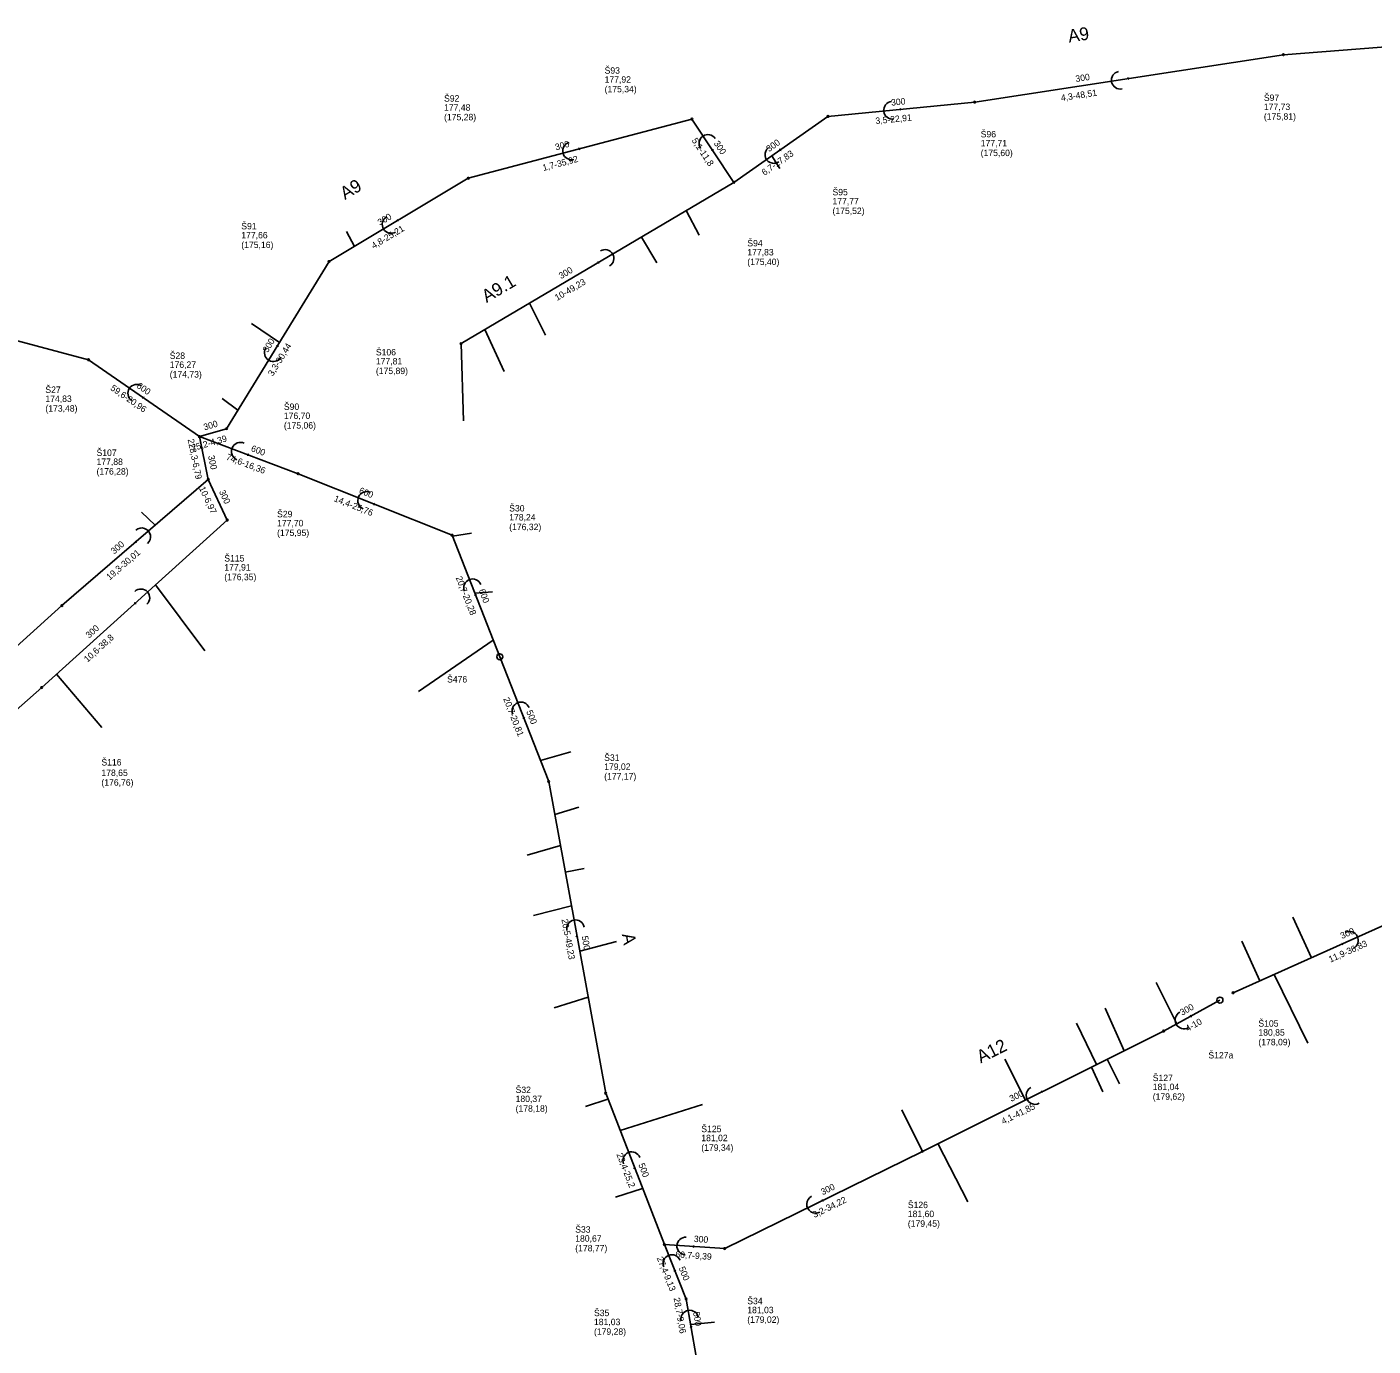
# Model space of a CAD drawing. Extents: x -548529 to -543591, y -1201432 to -1192608.
# Drawn here: x -546811.8 to -546602.8, y -1195130.1 to -1194925.2 of the extents above; entities that cross this region are included whole.
import ezdxf

# ---------------------------------------------------------------- set-up
doc = ezdxf.new("R2010")
doc.units = 0
for name, color, linetype in [('C3D_Bod-Značky', 7, 'Continuous'), ('C3D_Koridor', 7, 'Continuous'), ('C3D_Křižovatka', 7, 'Continuous'), ('C3D_Netisknutelná', 7, 'Continuous'), ('C3D_PP-zobrazeni v PR', 7, 'Continuous'), ('C3D_PR-Popisek', 7, 'Continuous'), ('C3D_SPR-Popisek', 7, 'Continuous'), ('C3D_Tlakove_potrubi_Popis', 7, 'Continuous'), ('C3D_ZPR-Formaty', 7, 'Continuous')]:
    doc.layers.add(name, color=color, linetype=linetype)

# ---------------------------------------------------------------- blocks, each defined once
blk = doc.blocks.new('100')
at = {"layer": 'Defpoints'}
blk.add_circle((0, 0), 0.127, dxfattribs=at)
blk = doc.blocks.new('101')
at = {"layer": 'Defpoints'}
blk.add_circle((0, 0), 0.463, dxfattribs=at)
blk = doc.blocks.new('91')
at = {"layer": 'Defpoints'}
blk.add_lwpolyline([(0.08, 0.14), (0.19, 0), (0.08, -0.14)], dxfattribs=at)
blk.add_arc((1.37, 0), 1.37, 270, 90, dxfattribs=at)
blk = doc.blocks.new('86')
at = {"layer": 'Defpoints'}
blk.add_lwpolyline([(0.08, 0.14), (0.19, 0), (0.08, -0.14)], dxfattribs=at)
blk.add_arc((1.37, 0), 1.37, 270, 90, dxfattribs=at)

msp = doc.modelspace()

# ---------------------------------------------------------------- linework, layer by layer
at = {"layer": 'C3D_Bod-Značky'}
for points in [[(-546569.03, -1194925.76), (-546616.67, -1194929.47)], [(-546616.67, -1194929.47), (-546664.62, -1194936.84)], [(-546664.62, -1194936.84), (-546687.417, -1194939.067)], [(-546708.549, -1194939.478), (-546743.272, -1194948.659)], [(-546702.016, -1194949.3), (-546708.549, -1194939.478)], [(-546687.417, -1194939.067), (-546702.016, -1194949.3)], [(-546743.272, -1194948.659), (-546764.903, -1194961.605)], [(-546744.402, -1194974.344), (-546702.016, -1194949.3)], [(-546764.903, -1194961.605), (-546780.799, -1194987.561)], [(-546802.25, -1194976.86), (-546840.07, -1194966.76)], [(-546785.018, -1194988.791), (-546802.25, -1194976.86)], [(-546780.799, -1194987.561), (-546785.018, -1194988.791)], [(-546783.658, -1194995.444), (-546785.018, -1194988.791)], [(-546769.704, -1194994.556), (-546785.018, -1194988.791)], [(-546806.389, -1195015.041), (-546783.658, -1194995.444)], [(-546780.716, -1195001.768), (-546783.658, -1194995.444)], [(-546745.786, -1195004.113), (-546769.704, -1194994.556)], [(-546809.519, -1195027.771), (-546780.716, -1195001.768)], [(-546738.383, -1195022.989), (-546745.786, -1195004.113)], [(-546843.032, -1195048.169), (-546806.389, -1195015.041)], [(-546730.785, -1195042.362), (-546738.383, -1195022.989)], [(-546846.428, -1195060.317), (-546809.519, -1195027.771)], [(-546721.933, -1195090.786), (-546730.785, -1195042.362)], [(-546624.49, -1195075.19), (-546590.87, -1195060.15)], [(-546626.536, -1195076.323), (-546635.297, -1195081.144)], [(-546635.297, -1195081.144), (-546672.747, -1195099.813)], [(-546712.823, -1195114.278), (-546721.933, -1195090.786)], [(-546672.747, -1195099.813), (-546703.452, -1195114.916)], [(-546703.452, -1195114.916), (-546712.823, -1195114.278)], [(-546709.433, -1195122.757), (-546712.823, -1195114.278)], [(-546707.859, -1195131.684), (-546709.433, -1195122.757)]]:
    msp.add_lwpolyline(points, dxfattribs=at)
at = {"layer": 'C3D_Koridor'}
for points in [[(-546696.143, -1194945.183), (-546694.865, -1194947.146)], [(-546709.426, -1194953.678), (-546707.408, -1194957.504)], [(-546760.958, -1194959.244), (-546762.19, -1194956.919)], [(-546716.39, -1194957.793), (-546713.995, -1194961.812)], [(-546733.783, -1194968.07), (-546731.27, -1194973.038)], [(-546772.597, -1194974.168), (-546776.951, -1194971.208)], [(-546740.712, -1194972.163), (-546737.689, -1194978.667)], [(-546744.402, -1194974.344), (-546743.999, -1194986.358)], [(-546779.046, -1194984.699), (-546781.5, -1194982.899)], [(-546791.877, -1195002.53), (-546793.999, -1195000.529)], [(-546745.721, -1195004.28), (-546742.788, -1195003.808)], [(-546791.842, -1195011.813), (-546784.198, -1195022.073)], [(-546742.261, -1195013.102), (-546739.522, -1195012.894)], [(-546739.387, -1195020.429), (-546751.015, -1195028.368)], [(-546807.233, -1195025.707), (-546800.207, -1195034.003)], [(-546732.07, -1195039.085), (-546727.356, -1195037.736)], [(-546729.851, -1195047.474), (-546726.086, -1195046.377)], [(-546728.966, -1195052.314), (-546734.109, -1195053.788)], [(-546728.207, -1195056.465), (-546725.26, -1195055.863)], [(-546727.25, -1195061.698), (-546733.169, -1195063.174)], [(-546612.322, -1195069.747), (-546615.228, -1195063.452)], [(-546620.318, -1195073.324), (-546623.13, -1195067.145)], [(-546725.966, -1195068.722), (-546720.244, -1195067.243)], [(-546618.1, -1195072.332), (-546612.91, -1195083.015)], [(-546633.221, -1195080.002), (-546636.447, -1195073.579)], [(-546724.661, -1195075.863), (-546729.917, -1195077.532)], [(-546641.392, -1195084.182), (-546644.35, -1195077.585)], [(-546645.705, -1195086.333), (-546648.802, -1195079.883)], [(-546656.758, -1195091.843), (-546659.942, -1195085.494)], [(-546644.059, -1195085.512), (-546642.138, -1195089.311)], [(-546646.484, -1195086.721), (-546644.697, -1195090.546)], [(-546721.58, -1195091.696), (-546725.054, -1195092.848)], [(-546719.682, -1195096.591), (-546706.895, -1195092.555)], [(-546672.747, -1195099.813), (-546675.928, -1195093.387)], [(-546670.326, -1195098.606), (-546665.677, -1195107.643)], [(-546716.2, -1195105.57), (-546720.426, -1195106.957)], [(-546708.732, -1195126.73), (-546705.026, -1195126.364)]]:
    msp.add_lwpolyline(points, dxfattribs=at)

# ---------------------------------------------------------------- block references
at = {"layer": 'C3D_PP-zobrazeni v PR'}
for name, p, xscale, yscale, rotation in [('100', (-546616.67, -1194929.47), 1.0098116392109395, 1.0098116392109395, -169.38969821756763), ('100', (-546664.62, -1194936.84), 1.0092050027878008, 1.0092050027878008, -168.88308178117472), ('100', (-546708.549, -1194939.478), 1.0296949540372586, 1.0296949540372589, 155.86620948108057), ('100', (-546687.417, -1194939.067), 1.0275072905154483, 1.027507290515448, -155.31089431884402), ('100', (-546743.272, -1194948.659), 1.0225848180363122, 1.0225848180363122, -154.18102564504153), ('100', (-546702.016, -1194949.3), 1.0073309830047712, 1.0073309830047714, 167.86109133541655), ('100', (-546764.903, -1194961.605), 0.999999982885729, 0.9999999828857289, -135), ('100', (-546744.402, -1194974.344), 1.0000000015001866, 1.0000000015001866, -149.00000017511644), ('100', (-546802.25, -1194976.86), 1.019856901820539, 1.0198569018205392, 153.606016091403), ('100', (-546780.799, -1194987.561), 1.000000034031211, 1.0000000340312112, -141.99999959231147), ('100', (-546785.018, -1194988.791), 0.9999999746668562, 0.999999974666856, 124.00000045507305), ('100', (-546783.658, -1194995.444), 0.999999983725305, 0.999999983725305, 109.00000122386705), ('100', (-546769.704, -1194994.556), 1.0275072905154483, 1.027507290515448, 155.31089431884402), ('100', (-546780.716, -1195001.768), 0.999999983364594, 0.9999999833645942, -101.0000002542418), ('100', (-546745.786, -1195004.113), 0.999999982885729, 0.9999999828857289, 135), ('100', (-546806.389, -1195015.041), 1.0000000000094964, 1.0000000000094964, -137.9999986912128), ('101', (-546738.383, -1195022.989), 1.0000000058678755, 1.0000000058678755, -68.00000099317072), ('100', (-546809.519, -1195027.771), 1.0000000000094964, 1.0000000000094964, -137.9999986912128), ('100', (-546730.785, -1195042.362), 0.9999999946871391, 0.9999999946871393, 106.00000024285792), ('100', (-546624.49, -1195075.19), 1.0169562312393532, 1.016956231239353, -153.02398354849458), ('101', (-546626.536, -1195076.323), 1.0037042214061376, 1.0037042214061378, 29.379208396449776), ('100', (-546635.297, -1195081.144), 1.0072562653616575, 1.0072562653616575, 28.76666512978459), ('100', (-546721.933, -1195090.786), 0.9999999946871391, 0.9999999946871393, 106.00000024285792), ('100', (-546672.747, -1195099.813), 1.0106518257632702, 1.0106518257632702, -151.83788426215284), ('100', (-546712.823, -1195114.278), 1.000000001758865, 1.000000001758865, 144.00000066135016), ('100', (-546703.452, -1195114.916), 1.0045862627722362, 1.0045862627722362, -166.82590928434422), ('100', (-546709.433, -1195122.757), 0.9999999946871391, 0.9999999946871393, 106.00000024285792)]:
    msp.add_blockref(name, p, dxfattribs=dict(at, xscale=xscale, yscale=yscale, rotation=rotation))
at = {"layer": 'C3D_SPR-Popisek'}
for name, p, xscale, yscale, rotation in [('91', (-546640.645, -1194933.155), 1.008377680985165, 1.0083776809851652, -168.37362119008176), ('91', (-546676.018, -1194937.954), 1.0011217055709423, 1.0011217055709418, -173.41739016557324), ('91', (-546705.282, -1194944.389), 0.9999999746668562, 0.999999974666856, 124.00000045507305), ('91', (-546725.91, -1194944.068), 0.999999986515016, 0.9999999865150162, -164.99999987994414), ('91', (-546694.716, -1194944.184), 1.000000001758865, 1.000000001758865, -144.00000066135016), ('91', (-546754.088, -1194955.132), 1.0000000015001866, 1.0000000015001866, -149.00000017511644), ('91', (-546723.209, -1194961.822), 1.0000000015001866, 1.0000000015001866, 30.99999982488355), ('91', (-546772.851, -1194974.583), 1.0000000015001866, 1.0000000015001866, -120.99999982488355), ('91', (-546793.634, -1194982.826), 0.9999999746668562, 0.999999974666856, 145.99999954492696), ('91', (-546777.361, -1194991.674), 1.0296949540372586, 1.0296949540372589, 155.86620948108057), ('91', (-546757.745, -1194999.334), 1.0275072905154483, 1.027507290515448, 155.31089431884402), ('91', (-546795.024, -1195005.242), 1.0000000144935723, 1.0000000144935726, 40.99999910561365), ('91', (-546742.085, -1195013.551), 1.0000000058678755, 1.0000000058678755, 111.99999900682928), ('86', (-546795.117, -1195014.77), 1.00000000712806, 1.00000000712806, 43.0000005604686), ('91', (-546734.584, -1195032.675), 1.0000000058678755, 1.0000000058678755, 111.99999900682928), ('91', (-546726.359, -1195066.574), 0.999999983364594, 0.9999999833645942, 101.0000002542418), ('91', (-546607.68, -1195067.67), 1.0169562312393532, 1.016956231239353, 26.97601645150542), ('91', (-546630.916, -1195078.734), 1.0037042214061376, 1.0037042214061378, -150.62079160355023), ('91', (-546654.022, -1195090.479), 1.0106518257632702, 1.0106518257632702, -151.83788426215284), ('91', (-546717.378, -1195102.532), 1.0000000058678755, 1.0000000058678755, 111.99999900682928), ('91', (-546688.1, -1195107.365), 1.0106518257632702, 1.0106518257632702, -151.83788426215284), ('91', (-546708.138, -1195114.597), 1.0002788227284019, 1.0002788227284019, 176.70930040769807), ('91', (-546711.128, -1195118.518), 1.0000000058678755, 1.0000000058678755, 111.99999900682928), ('91', (-546708.646, -1195127.22), 0.9999999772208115, 0.9999999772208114, 100.00000028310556)]:
    msp.add_blockref(name, p, dxfattribs=dict(at, xscale=xscale, yscale=yscale, rotation=rotation))

# ---------------------------------------------------------------- texts
at = {"layer": 'C3D_Křižovatka'}
for s, p in [('Š93', (-546722.099, -1194932.418)), ('Š92', (-546747.032, -1194936.759)), ('Š97', (-546619.71, -1194936.66)), ('Š96', (-546663.69, -1194942.32)), ('Š95', (-546686.707, -1194951.317)), ('Š91', (-546778.523, -1194956.605)), ('Š94', (-546699.936, -1194959.25)), ('Š106', (-546757.622, -1194976.184)), ('Š28', (-546789.638, -1194976.721)), ('Š27', (-546808.95, -1194982.01)), ('Š90', (-546771.909, -1194984.651)), ('Š107', (-546801.008, -1194991.794)), ('Š29', (-546772.964, -1195001.326)), ('Š30', (-546736.916, -1195000.423)), ('Š115', (-546781.166, -1195008.198)), ('Š476', (-546746.563, -1195026.989)), ('Š31', (-546722.165, -1195039.162)), ('Š116', (-546800.249, -1195039.881)), ('Š105', (-546620.56, -1195080.44)), ('Š127a', (-546628.326, -1195085.383)), ('Š127', (-546636.967, -1195088.904)), ('Š32', (-546735.923, -1195090.756)), ('Š125', (-546707.082, -1195096.836)), ('Š126', (-546675.007, -1195108.633)), ('Š33', (-546726.663, -1195112.448)), ('Š34', (-546699.943, -1195123.557)), ('Š35', (-546723.749, -1195125.414))]:
    msp.add_text(s, height=1, dxfattribs=at).set_placement(p)
at = {"layer": 'C3D_Netisknutelná'}
for s, rotation, p in [('A9', 8.74, (-546649.972, -1194927.592)), ('A9', 30.9, (-546762.424, -1194952.062)), ('A9.1', 30.58, (-546740.431, -1194968.049)), ('A', 280.36, (-546719.433, -1195066.109)), ('A12', 26.5, (-546663.684, -1195086.174))]:
    msp.add_text(s, height=2, rotation=rotation, dxfattribs=at).set_placement(p)
at = {"layer": 'C3D_PR-Popisek'}
for s, rotation, p in [('300', 8.74, (-546648.894, -1194933.718)), ('300', 5.58, (-546677.557, -1194937.398)), ('300', 14.81, (-546729.651, -1194944.337)), ('300', 303.63, (-546705.202, -1194943.237)), ('300', 35.03, (-546696.556, -1194944.616)), ('300', 30.9, (-546756.98, -1194956.045)), ('300', 30.58, (-546728.855, -1194964.348)), ('300', 58.52, (-546774.434, -1194975.822)), ('600', 325.3, (-546794.877, -1194981.118)), ('300', 16.25, (-546784.232, -1194987.833)), ('300', 281.55, (-546783.687, -1194991.804)), ('600', 339.37, (-546777.11, -1194991.016)), ('300', 294.95, (-546782.008, -1194997.34)), ('600', 338.22, (-546760.335, -1194997.548)), ('300', 40.77, (-546798.275, -1195007.117)), ('600', 291.41, (-546741.671, -1195012.681)), ('300', 42.08, (-546802.156, -1195020.178)), ('500', 291.41, (-546734.289, -1195031.502)), ('300', 24.1, (-546607.564, -1195066.85)), ('500', 280.36, (-546725.677, -1195066.422)), ('300', 28.82, (-546632.419, -1195078.761)), ('300', 26.5, (-546658.924, -1195092.139)), ('500', 291.2, (-546716.88, -1195101.873)), ('300', 26.19, (-546688.222, -1195106.643)), ('300', 356.11, (-546708.266, -1195113.886)), ('500', 291.79, (-546710.609, -1195117.935)), ('500', 280, (-546708.36, -1195124.821))]:
    msp.add_text(s, height=1, rotation=rotation, dxfattribs=at).set_placement(p)
at = {"layer": 'C3D_Tlakove_potrubi_Popis'}
for s, p in [('177,92 ', (-546722.099, -1194933.818)), ('(175,34)', (-546722.099, -1194935.318)), ('177,48 ', (-546747.032, -1194938.159)), ('177,73 ', (-546619.71, -1194938.06)), ('(175,28)', (-546747.032, -1194939.659)), ('(175,81)', (-546619.71, -1194939.56)), ('177,71 ', (-546663.69, -1194943.72)), ('(175,60)', (-546663.69, -1194945.22)), ('177,77 ', (-546686.707, -1194952.717)), ('(175,52)', (-546686.707, -1194954.217)), ('(175,16)', (-546778.523, -1194959.505)), ('177,66 ', (-546778.523, -1194958.005)), ('177,83 ', (-546699.936, -1194960.65)), ('(175,40)', (-546699.936, -1194962.15)), ('176,27 ', (-546789.638, -1194978.121)), ('177,81 ', (-546757.622, -1194977.584)), ('(174,73)', (-546789.638, -1194979.621)), ('(175,89)', (-546757.622, -1194979.084)), ('174,83 ', (-546808.95, -1194983.41)), ('(173,48)', (-546808.95, -1194984.91)), ('176,70 ', (-546771.909, -1194986.051)), ('(175,06)', (-546771.909, -1194987.551)), ('(176,28)', (-546801.008, -1194994.694)), ('177,88 ', (-546801.008, -1194993.194)), ('177,70 ', (-546772.964, -1195002.726)), ('(176,32)', (-546736.916, -1195003.323)), ('178,24 ', (-546736.916, -1195001.823)), ('(175,95)', (-546772.964, -1195004.226)), ('177,91 ', (-546781.166, -1195009.598)), ('(176,35)', (-546781.166, -1195011.098)), ('179,02 ', (-546722.165, -1195040.562)), ('(176,76)', (-546800.249, -1195043.011)), ('178,65 ', (-546800.249, -1195041.511)), ('(177,17)', (-546722.165, -1195042.062)), ('180,85 ', (-546620.56, -1195081.84)), ('(178,09)', (-546620.56, -1195083.34)), ('181,04 ', (-546636.967, -1195090.304)), ('180,37 ', (-546735.923, -1195092.156)), ('(179,62)', (-546636.967, -1195091.804)), ('(178,18)', (-546735.923, -1195093.656)), ('181,02 ', (-546707.082, -1195098.236)), ('(179,34)', (-546707.082, -1195099.736)), ('181,60 ', (-546675.007, -1195110.033)), ('(179,45)', (-546675.007, -1195111.533)), ('180,67 ', (-546726.663, -1195113.848)), ('(178,77)', (-546726.663, -1195115.348)), ('(179,02)', (-546699.943, -1195126.457)), ('181,03 ', (-546699.943, -1195124.957)), ('(179,28)', (-546723.749, -1195128.314)), ('181,03 ', (-546723.749, -1195126.814))]:
    msp.add_text(s, height=1, dxfattribs=at).set_placement(p)
at = {"layer": 'C3D_ZPR-Formaty'}
for s, rotation, p in [('4,3-48,51', 8.74, (-546651.157, -1194936.691)), ('3,5-22,91', 5.58, (-546679.988, -1194940.254)), ('5,1-11,8', 303.63, (-546708.614, -1194942.809)), ('1,7-35,92', 14.81, (-546731.594, -1194947.54)), ('6,7-17,83', 35.03, (-546697.274, -1194948.292)), ('4,8-25,21', 30.9, (-546757.958, -1194959.663)), ('10-49,23', 30.58, (-546729.47, -1194967.728)), ('3,3-30,44', 58.52, (-546773.62, -1194979.486)), ('59,6-20,96', 325.3, (-546798.944, -1194981.466)), ('228,3-6,79', 281.55, (-546786.87, -1194989.238)), ('75,2-4,39', 16.25, (-546786.092, -1194991.082)), ('74,6-16,36', 339.37, (-546780.981, -1194992.347)), ('10-6,97', 294.95, (-546785.117, -1194996.808)), ('14,4-25,76', 338.22, (-546764.23, -1194998.79)), ('19,3-30,01', 40.77, (-546798.956, -1195011.144)), ('20,7-20,28', 291.41, (-546745.244, -1195010.7)), ('10,6-38,8', 42.08, (-546802.412, -1195023.917)), ('20,7-20,81', 291.41, (-546737.862, -1195029.521)), ('20,5-49,23', 280.36, (-546728.801, -1195063.795)), ('11,9-36,83', 24.1, (-546609.378, -1195070.514)), ('4-10', 28.82, (-546631.559, -1195081.254)), ('4,1-41,85', 26.5, (-546660.186, -1195095.677)), ('23,4-25,2', 291.2, (-546720.281, -1195100.292)), ('3,2-34,22', 26.19, (-546689.497, -1195110.171)), ('27,4-9,13', 291.79, (-546714.022, -1195116.398)), ('60,7-9,39', 356.11, (-546711.135, -1195116.299)), ('28,7-9,06', 280, (-546711.388, -1195122.615))]:
    msp.add_text(s, height=1, rotation=rotation, dxfattribs=at).set_placement(p)

doc.saveas('drawing.dxf')
